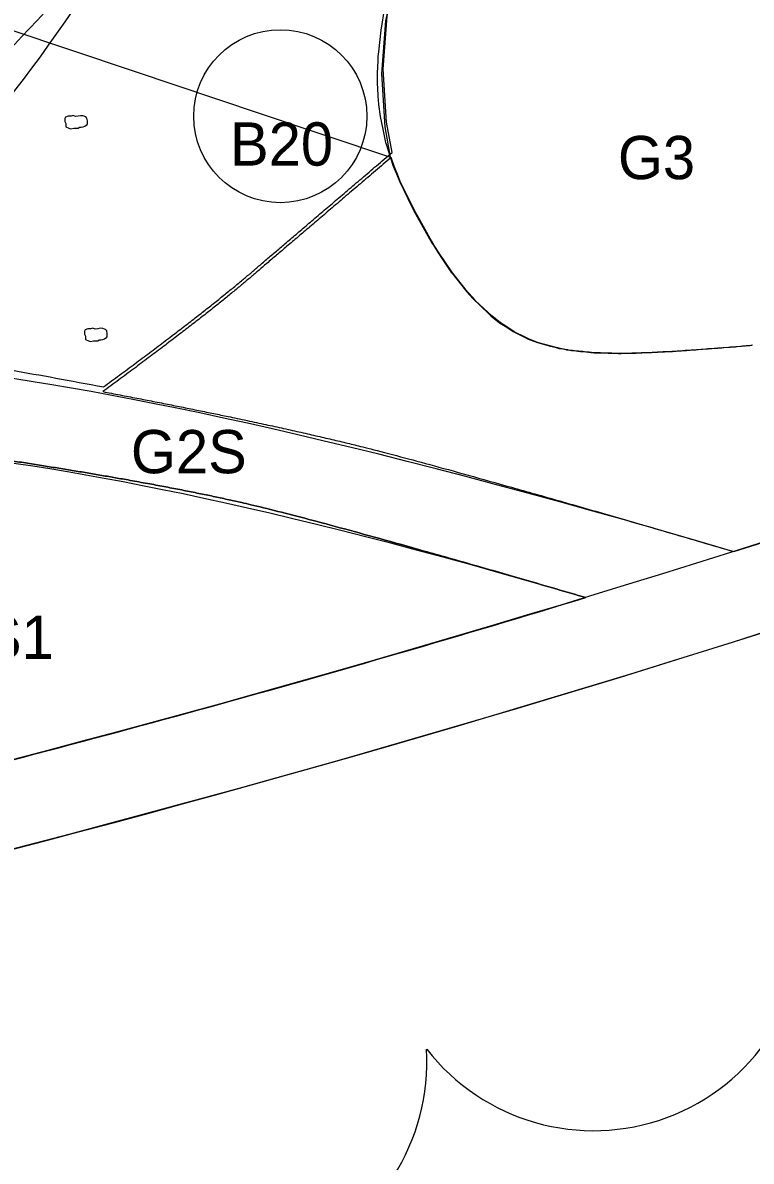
# Model space of a CAD drawing. Extents: x 0 to 512122, y 0 to 6212554.
# Drawn here: x 511598.68 to 511619.71, y 6211369.18 to 6211402.07 of the extents above; entities that cross this region are included whole.
import ezdxf

# ---------------------------------------------------------------- set-up
doc = ezdxf.new("R2010")
doc.units = 0
for name, color, linetype in [('_Marksten', 7, 'Continuous'), ('_Paths', 7, 'Continuous'), ('_S1_rabarber', 7, 'Continuous'), ('_Spredmingskorridor', 7, 'Continuous'), ('_Spredmingskorridor_hatch', 7, 'Continuous'), ('Clouds', 7, 'Continuous'), ('Tilgængelighed-1', 7, 'Continuous'), ('TV_U_AFM_Symbl_Gul', 7, 'Continuous'), ('TV_U_LYS_Mastenummer', 7, 'Continuous'), ('TV_U_LYS_Nyx330-Trafiksti-x2', 7, 'Continuous')]:
    doc.layers.add(name, color=color, linetype=linetype)

msp = doc.modelspace()

# ---------------------------------------------------------------- linework, layer by layer
at = {"layer": '_Marksten'}
for points in [[(511599.92, 6211399.063), (511600.012, 6211399.025), (511600.07, 6211399.008), (511600.152, 6211399.031), (511600.217, 6211399.029), (511600.282, 6211399.027), (511600.316, 6211399.058), (511600.362, 6211399.061), (511600.424, 6211399.067), (511600.475, 6211399.088), (511600.541, 6211399.134), (511600.553, 6211399.166), (511600.552, 6211399.195), (511600.551, 6211399.239), (511600.534, 6211399.313), (511600.503, 6211399.351), (511600.472, 6211399.366), (511600.422, 6211399.382), (511600.351, 6211399.389), (511600.276, 6211399.374), (511600.199, 6211399.367), (511600.134, 6211399.393), (511600.074, 6211399.374), (511600.026, 6211399.377), (511599.986, 6211399.371), (511599.912, 6211399.343), (511599.892, 6211399.303), (511599.892, 6211399.217), (511599.922, 6211399.162)], [(511600.488, 6211392.919), (511600.58, 6211392.881), (511600.638, 6211392.864), (511600.72, 6211392.887), (511600.785, 6211392.885), (511600.85, 6211392.883), (511600.884, 6211392.913), (511600.93, 6211392.917), (511600.992, 6211392.922), (511601.044, 6211392.944), (511601.109, 6211392.99), (511601.121, 6211393.022), (511601.121, 6211393.05), (511601.12, 6211393.095), (511601.103, 6211393.168), (511601.071, 6211393.207), (511601.041, 6211393.222), (511600.99, 6211393.237), (511600.919, 6211393.245), (511600.844, 6211393.23), (511600.767, 6211393.222), (511600.702, 6211393.249), (511600.642, 6211393.23), (511600.595, 6211393.232), (511600.554, 6211393.227), (511600.48, 6211393.199), (511600.461, 6211393.159), (511600.461, 6211393.073), (511600.49, 6211393.017)]]:
    msp.add_lwpolyline(points, close=True, dxfattribs=at)
at = {"layer": '_Paths'}
for centre, radius, start, end in [((511490.629, 6211792.585), 425.663, 281.76765, 290.60954), ((511490.629, 6211792.585), 428.163, 281.76765, 290.60954), ((511492.968, 6211783.33), 418.626, 281.73735, 290.80486)]:
    msp.add_arc(centre, radius, start, end, dxfattribs=at)
for points in [[(511619.187, 6211386.799), (511596.582, 6211393.479), (511585.389, 6211391.465), (511574.074, 6211393.08), (511564.353, 6211396.519), (511555.151, 6211400.37), (511543.395, 6211408.318), (511538.005, 6211417.069), (511534.527, 6211422.707), (511527.544, 6211428.597), (511520.899, 6211430.592), (511516.505, 6211433.059), (511513.01, 6211439.693), (511510.466, 6211444.112), (511507.781, 6211450.658), (511503.375, 6211454.994), (511500.203, 6211458.077), (511497.377, 6211464.569)], [(511614.911, 6211385.469), (511596.457, 6211390.915), (511585.439, 6211388.932), (511573.475, 6211390.64), (511563.453, 6211394.185), (511553.957, 6211398.16), (511541.549, 6211406.549), (511535.876, 6211415.757), (511532.609, 6211421.054), (511526.328, 6211426.352), (511519.916, 6211428.277), (511514.638, 6211431.24), (511510.82, 6211438.486), (511508.216, 6211443.009), (511505.662, 6211449.236), (511501.627, 6211453.206), (511498.108, 6211456.628), (511495.085, 6211463.571)]]:
    msp.add_open_spline(points, degree=3, dxfattribs=at)
at = {"layer": '_S1_rabarber'}
for points in [[(511619.756, 6211392.754), (511619.704, 6211392.749), (511619.572, 6211392.736), (511619.464, 6211392.726), (511619.428, 6211392.722), (511619.309, 6211392.711), (511619.289, 6211392.71), (511619.225, 6211392.705), (511619.13, 6211392.698), (511619.106, 6211392.696), (511619.085, 6211392.694), (511618.926, 6211392.683), (511618.895, 6211392.68), (511618.78, 6211392.672), (511618.751, 6211392.67), (511618.69, 6211392.665), (511618.68, 6211392.664), (511618.67, 6211392.664), (511618.574, 6211392.656), (511618.498, 6211392.651), (511618.459, 6211392.648), (511618.427, 6211392.646), (511618.314, 6211392.637), (511618.299, 6211392.636), (511618.184, 6211392.628), (511618.137, 6211392.624), (511618.057, 6211392.618), (511617.978, 6211392.612), (511617.939, 6211392.609), (511617.873, 6211392.604), (511617.812, 6211392.6), (511617.732, 6211392.594), (511617.668, 6211392.589), (511617.575, 6211392.582), (511617.502, 6211392.577), (511617.501, 6211392.577), (511617.471, 6211392.576), (511617.427, 6211392.573), (511617.354, 6211392.57), (511617.303, 6211392.568), (511617.241, 6211392.565), (511617.173, 6211392.561), (511617.122, 6211392.559), (511617.043, 6211392.555), (511617.007, 6211392.553), (511616.932, 6211392.55), (511616.859, 6211392.546), (511616.581, 6211392.533), (511616.547, 6211392.532), (511616.511, 6211392.53), (511616.415, 6211392.525), (511616.41, 6211392.525), (511616.361, 6211392.524), (511616.269, 6211392.523), (511616.189, 6211392.522), (511616.148, 6211392.521), (511616.099, 6211392.52), (511615.999, 6211392.519), (511615.985, 6211392.518), (511615.973, 6211392.518), (511615.9, 6211392.517), (511615.734, 6211392.522), (511615.69, 6211392.523), (511615.608, 6211392.525), (511615.365, 6211392.533), (511615.321, 6211392.534), (511615.209, 6211392.537), (511615.178, 6211392.538), (511615.176, 6211392.538), (511615.04, 6211392.552), (511614.961, 6211392.56), (511614.853, 6211392.571), (511614.82, 6211392.574), (511614.815, 6211392.575), (511614.732, 6211392.583), (511614.612, 6211392.596), (511614.555, 6211392.601), (511614.501, 6211392.607), (511614.44, 6211392.618), (511614.417, 6211392.622), (511614.408, 6211392.624), (511614.388, 6211392.627), (511614.296, 6211392.644), (511614.196, 6211392.661), (511614.181, 6211392.664), (511614.163, 6211392.669), (511614.134, 6211392.677), (511614.078, 6211392.692), (511613.94, 6211392.73), (511613.573, 6211392.829), (511613.284, 6211392.94), (511613.21, 6211392.977), (511612.869, 6211393.147), (511612.631, 6211393.303), (511612.476, 6211393.404), (511612.224, 6211393.602), (511611.88, 6211393.928), (511611.748, 6211394.053), (511611.693, 6211394.114), (511611.522, 6211394.302), (511611.487, 6211394.346), (511611.095, 6211394.841), (511611.09, 6211394.848), (511610.699, 6211395.421), (511610.563, 6211395.641), (511610.53, 6211395.694), (511610.45, 6211395.824), (511610.095, 6211396.462), (511609.99, 6211396.651), (511609.949, 6211396.734), (511609.581, 6211397.492), (511609.496, 6211397.7), (511609.459, 6211397.789), (511609.403, 6211397.927), (511609.32, 6211398.184)], [(511619.756, 6211392.754), (511619.704, 6211392.749), (511619.572, 6211392.736), (511619.464, 6211392.726), (511619.428, 6211392.722), (511619.309, 6211392.711), (511619.289, 6211392.71), (511619.225, 6211392.705), (511619.13, 6211392.698), (511619.106, 6211392.696), (511619.085, 6211392.694), (511618.926, 6211392.683), (511618.895, 6211392.68), (511618.78, 6211392.672), (511618.751, 6211392.67), (511618.69, 6211392.665), (511618.68, 6211392.664), (511618.67, 6211392.664), (511618.574, 6211392.656), (511618.498, 6211392.651), (511618.459, 6211392.648), (511618.427, 6211392.646), (511618.314, 6211392.637), (511618.299, 6211392.636), (511618.184, 6211392.628), (511618.137, 6211392.624), (511618.057, 6211392.618), (511617.978, 6211392.612), (511617.939, 6211392.609), (511617.873, 6211392.604), (511617.812, 6211392.6), (511617.732, 6211392.594), (511617.668, 6211392.589), (511617.575, 6211392.582), (511617.502, 6211392.577), (511617.471, 6211392.576), (511617.427, 6211392.573), (511617.354, 6211392.57), (511617.303, 6211392.568), (511617.241, 6211392.565), (511617.173, 6211392.561), (511617.122, 6211392.559), (511617.043, 6211392.555), (511617.007, 6211392.553), (511616.932, 6211392.55), (511616.859, 6211392.546), (511616.581, 6211392.533), (511616.547, 6211392.532), (511616.511, 6211392.53), (511616.415, 6211392.525), (511616.41, 6211392.525), (511616.361, 6211392.524), (511616.269, 6211392.523), (511616.189, 6211392.522), (511616.148, 6211392.521), (511616.099, 6211392.52), (511615.999, 6211392.519), (511615.985, 6211392.518), (511615.973, 6211392.518), (511615.9, 6211392.517), (511615.734, 6211392.522), (511615.69, 6211392.523), (511615.608, 6211392.525), (511615.365, 6211392.533), (511615.321, 6211392.534), (511615.209, 6211392.537), (511615.178, 6211392.538), (511615.176, 6211392.538), (511615.04, 6211392.552), (511614.961, 6211392.56), (511614.853, 6211392.571), (511614.82, 6211392.574), (511614.815, 6211392.575), (511614.732, 6211392.583), (511614.612, 6211392.596), (511614.555, 6211392.601), (511614.501, 6211392.607), (511614.44, 6211392.618), (511614.417, 6211392.622), (511614.408, 6211392.624), (511614.388, 6211392.627), (511614.296, 6211392.644), (511614.196, 6211392.661), (511614.181, 6211392.664), (511614.163, 6211392.669), (511614.134, 6211392.677), (511614.078, 6211392.692), (511613.94, 6211392.73), (511613.573, 6211392.829), (511613.284, 6211392.94), (511613.21, 6211392.977), (511612.869, 6211393.147), (511612.631, 6211393.303), (511612.476, 6211393.404), (511612.224, 6211393.602), (511611.88, 6211393.928), (511611.748, 6211394.053), (511611.693, 6211394.114), (511611.522, 6211394.302), (511611.487, 6211394.346), (511611.095, 6211394.841), (511611.09, 6211394.848), (511610.699, 6211395.421), (511610.563, 6211395.641), (511610.53, 6211395.694), (511610.45, 6211395.824), (511610.095, 6211396.462), (511609.99, 6211396.651), (511609.949, 6211396.734), (511609.581, 6211397.492), (511609.496, 6211397.7), (511609.459, 6211397.789), (511609.403, 6211397.927), (511609.32, 6211398.184)]]:
    msp.add_lwpolyline(points, dxfattribs=at)
for start, end in [(287.57872, 290.60954), (287.57872, 290.60954), (283.9464, 286.97593), (283.9464, 286.97593)]:
    msp.add_arc((511490.655, 6211792.581), 425.663, start, end, dxfattribs=at)
for points in [[(511609.32, 6211398.184), (511606.563, 6211395.831), (511603.834, 6211393.507), (511600.993, 6211391.415)], [(511609.32, 6211398.184), (511606.563, 6211395.831), (511603.834, 6211393.507), (511600.993, 6211391.415)], [(511600.993, 6211391.415), (511605.291, 6211390.598), (511610.956, 6211389.223), (511619.212, 6211386.795)], [(511600.993, 6211391.415), (511605.291, 6211390.598), (511610.956, 6211389.223), (511619.212, 6211386.795)], [(511598.166, 6211389.446), (511602.211, 6211388.829), (511607.308, 6211387.7), (511614.936, 6211385.465)], [(511614.936, 6211385.465), (511607.308, 6211387.7), (511602.211, 6211388.829), (511598.166, 6211389.446)]]:
    msp.add_open_spline(points, degree=2, dxfattribs=at)
at = {"layer": '_Spredmingskorridor'}
msp.add_lwpolyline([(511609.301, 6211398.194), (511609.142, 6211399.068), (511609.049, 6211400.601), (511609.159, 6211402.132), (511609.427, 6211403.323), (511609.827, 6211404.65), (511610.446, 6211406.002), (511610.976, 6211406.897), (511611.507, 6211407.793), (511612.576, 6211408.854), (511619.529, 6211414.959), (511618.625, 6211420.62)], dxfattribs=at)
for points in [[(511618.625, 6211420.62), (511606.029, 6211410.569), (511596.93, 6211398.178), (511583.32, 6211390.017), (511570.813, 6211390.175), (511555.007, 6211396.479), (511539.801, 6211408.822), (511527.664, 6211423.862), (511513.195, 6211431.425), (511508.403, 6211440.656), (511501.753, 6211451.707), (511492.266, 6211459.065), (511618.625, 6211420.62), (511492.266, 6211459.065)], [(511446.919, 6211452.593), (511459.024, 6211449.612), (511483.052, 6211444.239), (511494.738, 6211426.247), (511517.996, 6211408.457), (511535.129, 6211387.296), (511545.806, 6211384.873), (511574.749, 6211382.071), (511593.151, 6211386.596), (511609.301, 6211398.194), (511446.919, 6211452.593), (511609.301, 6211398.194)]]:
    msp.add_open_spline(points, degree=3, dxfattribs=at)
at = {"layer": '_Spredmingskorridor_hatch'}
msp.add_lwpolyline([(511609.343, 6211398.326), (511609.184, 6211399.201), (511609.091, 6211400.734), (511609.201, 6211402.265), (511609.468, 6211403.456), (511609.869, 6211404.782), (511610.488, 6211406.134), (511611.549, 6211407.926), (511612.618, 6211408.987), (511619.571, 6211415.091), (511618.667, 6211420.753)], dxfattribs=at)
for points, degree in [([(511618.667, 6211420.753), (511614.103, 6211417.732), (511605.185, 6211411.829), (511599.082, 6211399.357), (511592.448, 6211394.075), (511589.741, 6211392.592)], 3), ([(511601.01, 6211391.551), (511603.875, 6211393.659), (511606.609, 6211395.993), (511609.343, 6211398.326)], 2), ([(511589.741, 6211392.592), (511592.135, 6211392.703), (511595.326, 6211392.63), (511601.01, 6211391.551)], 2)]:
    msp.add_open_spline(points, degree=degree, dxfattribs=at)
at = {"layer": 'Clouds'}
for centre, start, end in [((511615.16, 6211376.162), 217.8425, 2.8425), ((511604.253, 6211372.051), 218.4607, 3.4607)]:
    msp.add_arc(centre, 6.1, start, end, dxfattribs=at)
at = {"layer": 'Tilgængelighed-1'}
msp.add_lwpolyline([(511609.128, 6211402.514), (511609.016, 6211401.861), (511608.95, 6211401.233), (511608.936, 6211401.099), (511608.931, 6211400.966), (511608.917, 6211400.627), (511608.917, 6211400.327), (511608.936, 6211399.996), (511608.947, 6211399.795), (511608.949, 6211399.76), (511608.955, 6211399.714), (511608.999, 6211399.361), (511609.076, 6211398.995), (511609.155, 6211398.617), (511609.163, 6211398.592), (511609.377, 6211397.931), (511609.433, 6211397.793), (511609.47, 6211397.704), (511609.555, 6211397.496), (511609.923, 6211396.738), (511609.964, 6211396.655), (511610.069, 6211396.466), (511610.424, 6211395.828), (511610.504, 6211395.698), (511610.537, 6211395.645), (511610.673, 6211395.425), (511611.064, 6211394.852), (511611.069, 6211394.845), (511611.461, 6211394.35), (511611.496, 6211394.306), (511611.667, 6211394.118), (511611.722, 6211394.057), (511611.854, 6211393.932), (511612.198, 6211393.606), (511612.45, 6211393.408), (511612.605, 6211393.307), (511612.843, 6211393.151), (511613.184, 6211392.981), (511613.258, 6211392.944), (511613.547, 6211392.833), (511613.914, 6211392.734), (511614.052, 6211392.696), (511614.108, 6211392.681), (511614.137, 6211392.673), (511614.155, 6211392.668), (511614.17, 6211392.665), (511614.27, 6211392.648), (511614.362, 6211392.631), (511614.382, 6211392.628), (511614.391, 6211392.626), (511614.414, 6211392.622), (511614.475, 6211392.611), (511614.529, 6211392.605), (511614.586, 6211392.6), (511614.706, 6211392.587), (511614.789, 6211392.579), (511614.794, 6211392.578), (511614.827, 6211392.575), (511614.935, 6211392.564), (511615.014, 6211392.556), (511615.082, 6211392.549), (511615.15, 6211392.542), (511615.152, 6211392.542), (511615.183, 6211392.541), (511615.295, 6211392.538), (511615.339, 6211392.537), (511615.582, 6211392.529), (511615.664, 6211392.527), (511615.708, 6211392.526), (511615.874, 6211392.521), (511615.947, 6211392.522), (511615.959, 6211392.522), (511615.973, 6211392.523), (511616.073, 6211392.524), (511616.122, 6211392.525), (511616.163, 6211392.526), (511616.243, 6211392.527), (511616.335, 6211392.528), (511616.384, 6211392.529), (511616.389, 6211392.529), (511616.485, 6211392.534), (511616.521, 6211392.536), (511616.555, 6211392.537), (511616.833, 6211392.55), (511616.906, 6211392.554), (511616.981, 6211392.557), (511617.017, 6211392.559), (511617.096, 6211392.563), (511617.147, 6211392.565), (511617.215, 6211392.569), (511617.277, 6211392.572), (511617.328, 6211392.574), (511617.401, 6211392.577), (511617.445, 6211392.58), (511617.475, 6211392.581), (511617.476, 6211392.581), (511617.549, 6211392.586), (511617.642, 6211392.593), (511617.706, 6211392.598), (511617.786, 6211392.604), (511617.847, 6211392.608), (511617.913, 6211392.613), (511617.952, 6211392.616), (511618.031, 6211392.622), (511618.111, 6211392.628), (511618.158, 6211392.632), (511618.273, 6211392.64), (511618.288, 6211392.641), (511618.401, 6211392.65), (511618.433, 6211392.652), (511618.472, 6211392.655), (511618.548, 6211392.66), (511618.644, 6211392.668), (511618.654, 6211392.668), (511618.664, 6211392.669), (511618.725, 6211392.674), (511618.754, 6211392.676), (511618.869, 6211392.684), (511618.9, 6211392.687), (511619.059, 6211392.698), (511619.08, 6211392.7), (511619.104, 6211392.702), (511619.199, 6211392.709), (511619.263, 6211392.714), (511619.283, 6211392.715), (511619.402, 6211392.726), (511619.438, 6211392.73), (511619.492, 6211392.735), (511619.546, 6211392.74), (511619.678, 6211392.753), (511619.73, 6211392.758)], dxfattribs=at)
at = {"layer": 'TV_U_LYS_Mastenummer'}
msp.add_circle((511606.116, 6211399.374), 2.5, dxfattribs=at)
msp.add_circle((511606.116, 6211399.374), 2.5, dxfattribs=at)
at = {"layer": 'TV_U_LYS_Nyx330-Trafiksti-x2'}
msp.add_lwpolyline([(511609.128, 6211402.514), (511609.016, 6211401.861), (511608.95, 6211401.233), (511608.936, 6211401.099), (511608.931, 6211400.966), (511608.917, 6211400.627), (511608.917, 6211400.327), (511608.936, 6211399.996), (511608.947, 6211399.795), (511608.949, 6211399.76), (511608.955, 6211399.714), (511608.999, 6211399.361), (511609.076, 6211398.995), (511609.155, 6211398.617), (511609.163, 6211398.592), (511609.377, 6211397.931), (511609.433, 6211397.793), (511609.47, 6211397.704), (511609.555, 6211397.496), (511609.923, 6211396.738), (511609.964, 6211396.655), (511610.069, 6211396.466), (511610.424, 6211395.828), (511610.504, 6211395.698), (511610.537, 6211395.645), (511610.673, 6211395.425), (511611.064, 6211394.852), (511611.069, 6211394.845), (511611.461, 6211394.35), (511611.496, 6211394.306), (511611.667, 6211394.118), (511611.722, 6211394.057), (511611.854, 6211393.932), (511612.198, 6211393.606), (511612.45, 6211393.408), (511612.605, 6211393.307), (511612.843, 6211393.151), (511613.184, 6211392.981), (511613.258, 6211392.944), (511613.547, 6211392.833), (511613.914, 6211392.734), (511614.052, 6211392.696), (511614.108, 6211392.681), (511614.137, 6211392.673), (511614.155, 6211392.668), (511614.17, 6211392.665), (511614.27, 6211392.648), (511614.362, 6211392.631), (511614.382, 6211392.628), (511614.391, 6211392.626), (511614.414, 6211392.622), (511614.475, 6211392.611), (511614.529, 6211392.605), (511614.586, 6211392.6), (511614.706, 6211392.587), (511614.789, 6211392.579), (511614.794, 6211392.578), (511614.827, 6211392.575), (511614.935, 6211392.564), (511615.014, 6211392.556), (511615.082, 6211392.549), (511615.15, 6211392.542), (511615.152, 6211392.542), (511615.183, 6211392.541), (511615.295, 6211392.538), (511615.339, 6211392.537), (511615.582, 6211392.529), (511615.664, 6211392.527), (511615.708, 6211392.526), (511615.874, 6211392.521), (511615.947, 6211392.522), (511615.959, 6211392.522), (511615.973, 6211392.523), (511616.073, 6211392.524), (511616.122, 6211392.525), (511616.163, 6211392.526), (511616.243, 6211392.527), (511616.335, 6211392.528), (511616.384, 6211392.529), (511616.389, 6211392.529), (511616.485, 6211392.534), (511616.521, 6211392.536), (511616.555, 6211392.537), (511616.833, 6211392.55), (511616.906, 6211392.554), (511616.981, 6211392.557), (511617.017, 6211392.559), (511617.096, 6211392.563), (511617.147, 6211392.565), (511617.215, 6211392.569), (511617.277, 6211392.572), (511617.328, 6211392.574), (511617.401, 6211392.577), (511617.445, 6211392.58), (511617.475, 6211392.581), (511617.476, 6211392.581), (511617.549, 6211392.586), (511617.642, 6211392.593), (511617.706, 6211392.598), (511617.786, 6211392.604), (511617.847, 6211392.608), (511617.913, 6211392.613), (511617.952, 6211392.616), (511618.031, 6211392.622), (511618.111, 6211392.628), (511618.158, 6211392.632), (511618.273, 6211392.64), (511618.288, 6211392.641), (511618.401, 6211392.65), (511618.433, 6211392.652), (511618.472, 6211392.655), (511618.548, 6211392.66), (511618.644, 6211392.668), (511618.654, 6211392.668), (511618.664, 6211392.669), (511618.725, 6211392.674), (511618.754, 6211392.676), (511618.869, 6211392.684), (511618.9, 6211392.687), (511619.059, 6211392.698), (511619.08, 6211392.7), (511619.104, 6211392.702), (511619.199, 6211392.709), (511619.263, 6211392.714), (511619.283, 6211392.715), (511619.402, 6211392.726), (511619.438, 6211392.73), (511619.492, 6211392.735), (511619.546, 6211392.74), (511619.678, 6211392.753), (511619.73, 6211392.758)], dxfattribs=at)

# ---------------------------------------------------------------- texts
at = {"layer": 'TV_U_AFM_Symbl_Gul'}
for s, p in [('B20', (511604.666, 6211397.946)), ('G3', (511615.865, 6211397.554)), ('G2S', (511601.802, 6211389.057)), ('S1', (511597.53, 6211383.695))]:
    msp.add_text(s, height=1.25, dxfattribs=at).set_placement(p)

doc.saveas('drawing.dxf')
